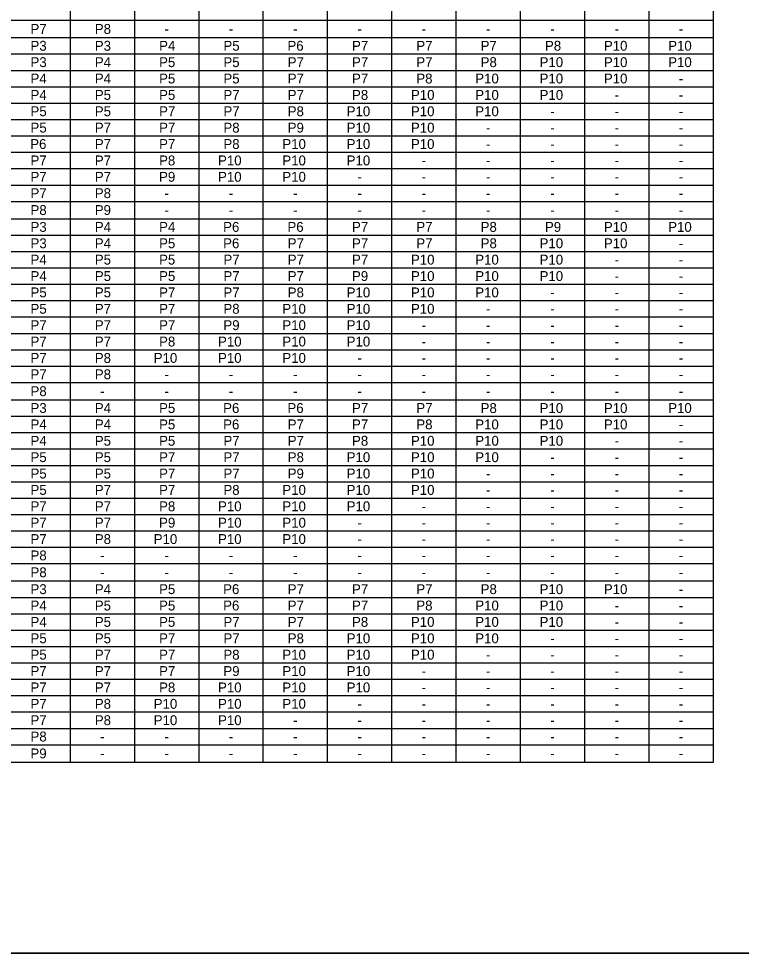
# Model space of a CAD drawing. Extents: x 637580 to 641008, y 294594 to 295782.
# Drawn here: x 639502.8 to 639722, y 295202.6 to 295486.4 of the extents above; entities that cross this region are included whole.
import ezdxf

# ---------------------------------------------------------------- set-up
doc = ezdxf.new("R2010")
doc.units = 0
doc.layers.add('1', color=7, linetype='Continuous')
doc.layers.add('2', color=7, linetype='Continuous')

msp = doc.modelspace()

# ---------------------------------------------------------------- linework, layer by layer
at = {"layer": '1'}
for p, q in [((639713.6, 295260.68), (639713.6, 295724.98)), ((639346.67, 295480.64), (639713.6, 295480.64)), ((639346.67, 295425.65), (639713.6, 295425.65)), ((639346.67, 295370.66), (639713.6, 295370.66)), ((639346.67, 295315.67), (639713.6, 295315.67)), ((639346.67, 295260.68), (639713.6, 295260.68)), ((640088.31, 295202.63), (639302.31, 295202.63)), ((639302.31, 295202.63), (639888.31, 295202.63))]:
    msp.add_line(p, q, dxfattribs=at)
at = {"layer": '2'}
for p, q in [((639518.52, 295260.68), (639518.52, 295709.96)), ((639538.03, 295260.68), (639538.03, 295709.96)), ((639557.54, 295260.68), (639557.54, 295709.96)), ((639577.04, 295260.68), (639577.04, 295709.96)), ((639596.55, 295260.68), (639596.55, 295709.96)), ((639616.06, 295260.68), (639616.06, 295709.96)), ((639635.57, 295260.68), (639635.57, 295709.96)), ((639655.07, 295260.68), (639655.07, 295709.96)), ((639674.58, 295260.68), (639674.58, 295709.96)), ((639694.09, 295260.68), (639694.09, 295709.96)), ((639373.47, 295485.9), (639713.6, 295485.9)), ((639373.47, 295475.66), (639713.6, 295475.66)), ((639373.47, 295470.69), (639713.6, 295470.69)), ((639373.47, 295465.72), (639713.6, 295465.72)), ((639373.47, 295460.75), (639713.6, 295460.75)), ((639373.47, 295455.77), (639713.6, 295455.77)), ((639373.47, 295450.8), (639713.6, 295450.8)), ((639373.47, 295445.83), (639713.6, 295445.83)), ((639373.47, 295440.86), (639713.6, 295440.86)), ((639373.47, 295435.88), (639713.6, 295435.88)), ((639373.47, 295430.91), (639713.6, 295430.91)), ((639373.47, 295420.67), (639713.6, 295420.67)), ((639373.47, 295415.7), (639713.6, 295415.7)), ((639373.47, 295410.73), (639713.6, 295410.73)), ((639373.47, 295405.76), (639713.6, 295405.76)), ((639373.47, 295400.78), (639713.6, 295400.78)), ((639373.47, 295395.81), (639713.6, 295395.81)), ((639373.47, 295390.84), (639713.6, 295390.84)), ((639373.47, 295385.87), (639713.6, 295385.87)), ((639373.47, 295380.89), (639713.6, 295380.89)), ((639373.47, 295375.92), (639713.6, 295375.92)), ((639373.47, 295365.68), (639713.6, 295365.68)), ((639373.47, 295360.71), (639713.6, 295360.71)), ((639373.47, 295355.74), (639713.6, 295355.74)), ((639373.47, 295350.77), (639713.6, 295350.77)), ((639373.47, 295345.79), (639713.6, 295345.79)), ((639373.47, 295340.82), (639713.6, 295340.82)), ((639373.47, 295335.85), (639713.6, 295335.85)), ((639373.47, 295330.88), (639713.6, 295330.88)), ((639373.47, 295325.9), (639713.6, 295325.9)), ((639373.47, 295320.93), (639713.6, 295320.93)), ((639373.47, 295310.69), (639713.6, 295310.69)), ((639373.47, 295305.72), (639713.6, 295305.72)), ((639373.47, 295300.75), (639713.6, 295300.75)), ((639373.47, 295295.78), (639713.6, 295295.78)), ((639373.47, 295290.8), (639713.6, 295290.8)), ((639373.47, 295285.83), (639713.6, 295285.83)), ((639373.47, 295280.86), (639713.6, 295280.86)), ((639373.47, 295275.89), (639713.6, 295275.89)), ((639373.47, 295270.91), (639713.6, 295270.91)), ((639373.47, 295265.94), (639713.6, 295265.94))]:
    msp.add_line(p, q, dxfattribs=at)

# ---------------------------------------------------------------- texts
at = {"layer": '1'}
for s, p in [('P7', (639506.42, 295481.77)), ('P8', (639525.93, 295481.77)), ('-', (639547.05, 295481.77)), ('-', (639566.56, 295481.77)), ('-', (639586.07, 295481.77)), ('-', (639605.57, 295481.77)), ('-', (639625.08, 295481.77)), ('-', (639644.59, 295481.77)), ('-', (639664.1, 295481.77)), ('-', (639683.6, 295481.77)), ('-', (639703.11, 295481.77)), ('P3', (639506.42, 295476.65)), ('P3', (639525.93, 295476.65)), ('P4', (639545.43, 295476.65)), ('P5', (639564.94, 295476.65)), ('P6', (639584.36, 295476.65)), ('P7', (639603.95, 295476.65)), ('P7', (639623.46, 295476.65)), ('P7', (639642.97, 295476.65)), ('P8', (639662.48, 295476.65)), ('P10', (639680.35, 295476.65)), ('P10', (639699.86, 295476.65)), ('P3', (639506.42, 295471.68)), ('P4', (639525.93, 295471.68)), ('P5', (639545.43, 295471.68)), ('P5', (639564.94, 295471.68)), ('P7', (639584.45, 295471.68)), ('P7', (639603.95, 295471.68)), ('P7', (639623.46, 295471.68)), ('P8', (639642.97, 295471.68)), ('P10', (639660.85, 295471.68)), ('P10', (639680.35, 295471.68)), ('P10', (639699.86, 295471.68)), ('P4', (639506.42, 295466.71)), ('P4', (639525.93, 295466.71)), ('P5', (639545.43, 295466.71)), ('P5', (639564.94, 295466.71)), ('P7', (639584.45, 295466.71)), ('P7', (639603.95, 295466.71)), ('P8', (639623.46, 295466.71)), ('P10', (639641.34, 295466.71)), ('P10', (639660.85, 295466.71)), ('P10', (639680.35, 295466.71)), ('-', (639703.11, 295466.71)), ('P4', (639506.42, 295461.73)), ('P5', (639525.93, 295461.73)), ('P5', (639545.43, 295461.73)), ('P7', (639564.94, 295461.73)), ('P7', (639584.45, 295461.73)), ('P8', (639603.95, 295461.73)), ('P10', (639621.83, 295461.73)), ('P10', (639641.34, 295461.73)), ('P10', (639660.85, 295461.73)), ('-', (639683.6, 295461.73)), ('-', (639703.11, 295461.73)), ('P5', (639506.42, 295456.76)), ('P5', (639525.93, 295456.76)), ('P7', (639545.43, 295456.76)), ('P7', (639564.94, 295456.76)), ('P8', (639584.45, 295456.76)), ('P10', (639602.33, 295456.76)), ('P10', (639621.83, 295456.76)), ('P10', (639641.34, 295456.76)), ('-', (639664.1, 295456.76)), ('-', (639683.6, 295456.76)), ('-', (639703.11, 295456.76)), ('P5', (639506.42, 295451.79)), ('P7', (639525.93, 295451.79)), ('P7', (639545.43, 295451.79)), ('P8', (639564.94, 295451.79)), ('P9', (639584.44, 295451.79)), ('P10', (639602.33, 295451.79)), ('P10', (639621.83, 295451.79)), ('-', (639644.59, 295451.79)), ('-', (639664.1, 295451.79)), ('-', (639683.6, 295451.79)), ('-', (639703.11, 295451.79)), ('P6', (639506.33, 295446.82)), ('P7', (639525.93, 295446.82)), ('P7', (639545.43, 295446.82)), ('P8', (639564.94, 295446.82)), ('P10', (639582.82, 295446.82)), ('P10', (639602.33, 295446.82)), ('P10', (639621.83, 295446.82)), ('-', (639644.59, 295446.82)), ('-', (639664.1, 295446.82)), ('-', (639683.6, 295446.82)), ('-', (639703.11, 295446.82)), ('P7', (639506.42, 295441.84)), ('P7', (639525.93, 295441.84)), ('P8', (639545.43, 295441.84)), ('P10', (639563.31, 295441.84)), ('P10', (639582.82, 295441.84)), ('P10', (639602.33, 295441.84)), ('-', (639625.08, 295441.84)), ('-', (639644.59, 295441.84)), ('-', (639664.1, 295441.84)), ('-', (639683.6, 295441.84)), ('-', (639703.11, 295441.84)), ('P7', (639506.42, 295436.87)), ('P7', (639525.93, 295436.87)), ('P9', (639545.42, 295436.87)), ('P10', (639563.31, 295436.87)), ('P10', (639582.82, 295436.87)), ('-', (639605.57, 295436.87)), ('-', (639625.08, 295436.87)), ('-', (639644.59, 295436.87)), ('-', (639664.1, 295436.87)), ('-', (639683.6, 295436.87)), ('-', (639703.11, 295436.87)), ('P7', (639506.42, 295431.9)), ('P8', (639525.93, 295431.9)), ('-', (639547.05, 295431.9)), ('-', (639566.56, 295431.9)), ('-', (639586.07, 295431.9)), ('-', (639605.57, 295431.9)), ('-', (639625.08, 295431.9)), ('-', (639644.59, 295431.9)), ('-', (639664.1, 295431.9)), ('-', (639683.6, 295431.9)), ('-', (639703.11, 295431.9)), ('P8', (639506.42, 295426.78)), ('P9', (639525.91, 295426.78)), ('-', (639547.05, 295426.78)), ('-', (639566.56, 295426.78)), ('-', (639586.07, 295426.78)), ('-', (639605.57, 295426.78)), ('-', (639625.08, 295426.78)), ('-', (639644.59, 295426.78)), ('-', (639664.1, 295426.78)), ('-', (639683.6, 295426.78)), ('-', (639703.11, 295426.78)), ('P3', (639506.42, 295421.66)), ('P4', (639525.93, 295421.66)), ('P4', (639545.43, 295421.66)), ('P6', (639564.86, 295421.66)), ('P6', (639584.36, 295421.66)), ('P7', (639603.95, 295421.66)), ('P7', (639623.46, 295421.66)), ('P8', (639642.97, 295421.66)), ('P9', (639662.47, 295421.66)), ('P10', (639680.35, 295421.66)), ('P10', (639699.86, 295421.66)), ('P3', (639506.42, 295416.69)), ('P4', (639525.93, 295416.69)), ('P5', (639545.43, 295416.69)), ('P6', (639564.86, 295416.69)), ('P7', (639584.45, 295416.69)), ('P7', (639603.95, 295416.69)), ('P7', (639623.46, 295416.69)), ('P8', (639642.97, 295416.69)), ('P10', (639660.85, 295416.69)), ('P10', (639680.35, 295416.69)), ('-', (639703.11, 295416.69)), ('P4', (639506.42, 295411.72)), ('P5', (639525.93, 295411.72)), ('P5', (639545.43, 295411.72)), ('P7', (639564.94, 295411.72)), ('P7', (639584.45, 295411.72)), ('P7', (639603.95, 295411.72)), ('P10', (639621.83, 295411.72)), ('P10', (639641.34, 295411.72)), ('P10', (639660.85, 295411.72)), ('-', (639683.6, 295411.72)), ('-', (639703.11, 295411.72)), ('P4', (639506.42, 295406.74)), ('P5', (639525.93, 295406.74)), ('P5', (639545.43, 295406.74)), ('P7', (639564.94, 295406.74)), ('P7', (639584.45, 295406.74)), ('P9', (639603.94, 295406.74)), ('P10', (639621.83, 295406.74)), ('P10', (639641.34, 295406.74)), ('P10', (639660.85, 295406.74)), ('-', (639683.6, 295406.74)), ('-', (639703.11, 295406.74)), ('P5', (639506.42, 295401.77)), ('P5', (639525.93, 295401.77)), ('P7', (639545.43, 295401.77)), ('P7', (639564.94, 295401.77)), ('P8', (639584.45, 295401.77)), ('P10', (639602.33, 295401.77)), ('P10', (639621.83, 295401.77)), ('P10', (639641.34, 295401.77)), ('-', (639664.1, 295401.77)), ('-', (639683.6, 295401.77)), ('-', (639703.11, 295401.77)), ('P5', (639506.42, 295396.8)), ('P7', (639525.93, 295396.8)), ('P7', (639545.43, 295396.8)), ('P8', (639564.94, 295396.8)), ('P10', (639582.82, 295396.8)), ('P10', (639602.33, 295396.8)), ('P10', (639621.83, 295396.8)), ('-', (639644.59, 295396.8)), ('-', (639664.1, 295396.8)), ('-', (639683.6, 295396.8)), ('-', (639703.11, 295396.8)), ('P7', (639506.42, 295391.83)), ('P7', (639525.93, 295391.83)), ('P7', (639545.43, 295391.83)), ('P9', (639564.93, 295391.83)), ('P10', (639582.82, 295391.83)), ('P10', (639602.33, 295391.83)), ('-', (639625.08, 295391.83)), ('-', (639644.59, 295391.83)), ('-', (639664.1, 295391.83)), ('-', (639683.6, 295391.83)), ('-', (639703.11, 295391.83)), ('P7', (639506.42, 295386.85)), ('P7', (639525.93, 295386.85)), ('P8', (639545.43, 295386.85)), ('P10', (639563.31, 295386.85)), ('P10', (639582.82, 295386.85)), ('P10', (639602.33, 295386.85)), ('-', (639625.08, 295386.85)), ('-', (639644.59, 295386.85)), ('-', (639664.1, 295386.85)), ('-', (639683.6, 295386.85)), ('-', (639703.11, 295386.85)), ('P7', (639506.42, 295381.88)), ('P8', (639525.93, 295381.88)), ('P10', (639543.8, 295381.88)), ('P10', (639563.31, 295381.88)), ('P10', (639582.82, 295381.88)), ('-', (639605.57, 295381.88)), ('-', (639625.08, 295381.88)), ('-', (639644.59, 295381.88)), ('-', (639664.1, 295381.88)), ('-', (639683.6, 295381.88)), ('-', (639703.11, 295381.88)), ('P7', (639506.42, 295376.91)), ('P8', (639525.93, 295376.91)), ('-', (639547.05, 295376.91)), ('-', (639566.56, 295376.91)), ('-', (639586.07, 295376.91)), ('-', (639605.57, 295376.91)), ('-', (639625.08, 295376.91)), ('-', (639644.59, 295376.91)), ('-', (639664.1, 295376.91)), ('-', (639683.6, 295376.91)), ('-', (639703.11, 295376.91)), ('P8', (639506.42, 295371.79)), ('-', (639527.54, 295371.79)), ('-', (639547.05, 295371.79)), ('-', (639566.56, 295371.79)), ('-', (639586.07, 295371.79)), ('-', (639605.57, 295371.79)), ('-', (639625.08, 295371.79)), ('-', (639644.59, 295371.79)), ('-', (639664.1, 295371.79)), ('-', (639683.6, 295371.79)), ('-', (639703.11, 295371.79)), ('P3', (639506.42, 295366.67)), ('P4', (639525.93, 295366.67)), ('P5', (639545.43, 295366.67)), ('P6', (639564.86, 295366.67)), ('P6', (639584.36, 295366.67)), ('P7', (639603.95, 295366.67)), ('P7', (639623.46, 295366.67)), ('P8', (639642.97, 295366.67)), ('P10', (639660.85, 295366.67)), ('P10', (639680.35, 295366.67)), ('P10', (639699.86, 295366.67)), ('P4', (639506.42, 295361.7)), ('P4', (639525.93, 295361.7)), ('P5', (639545.43, 295361.7)), ('P6', (639564.86, 295361.7)), ('P7', (639584.45, 295361.7)), ('P7', (639603.95, 295361.7)), ('P8', (639623.46, 295361.7)), ('P10', (639641.34, 295361.7)), ('P10', (639660.85, 295361.7)), ('P10', (639680.35, 295361.7)), ('-', (639703.11, 295361.7)), ('P4', (639506.42, 295356.73)), ('P5', (639525.93, 295356.73)), ('P5', (639545.43, 295356.73)), ('P7', (639564.94, 295356.73)), ('P7', (639584.45, 295356.73)), ('P8', (639603.95, 295356.73)), ('P10', (639621.83, 295356.73)), ('P10', (639641.34, 295356.73)), ('P10', (639660.85, 295356.73)), ('-', (639683.6, 295356.73)), ('-', (639703.11, 295356.73)), ('P5', (639506.42, 295351.75)), ('P5', (639525.93, 295351.75)), ('P7', (639545.43, 295351.75)), ('P7', (639564.94, 295351.75)), ('P8', (639584.45, 295351.75)), ('P10', (639602.33, 295351.75)), ('P10', (639621.83, 295351.75)), ('P10', (639641.34, 295351.75)), ('-', (639664.1, 295351.75)), ('-', (639683.6, 295351.75)), ('-', (639703.11, 295351.75)), ('P5', (639506.42, 295346.78)), ('P5', (639525.93, 295346.78)), ('P7', (639545.43, 295346.78)), ('P7', (639564.94, 295346.78)), ('P9', (639584.44, 295346.78)), ('P10', (639602.33, 295346.78)), ('P10', (639621.83, 295346.78)), ('-', (639644.59, 295346.78)), ('-', (639664.1, 295346.78)), ('-', (639683.6, 295346.78)), ('-', (639703.11, 295346.78)), ('P5', (639506.42, 295341.81)), ('P7', (639525.93, 295341.81)), ('P7', (639545.43, 295341.81)), ('P8', (639564.94, 295341.81)), ('P10', (639582.82, 295341.81)), ('P10', (639602.33, 295341.81)), ('P10', (639621.83, 295341.81)), ('-', (639644.59, 295341.81)), ('-', (639664.1, 295341.81)), ('-', (639683.6, 295341.81)), ('-', (639703.11, 295341.81)), ('P7', (639506.42, 295336.84)), ('P7', (639525.93, 295336.84)), ('P8', (639545.43, 295336.84)), ('P10', (639563.31, 295336.84)), ('P10', (639582.82, 295336.84)), ('P10', (639602.33, 295336.84)), ('-', (639625.08, 295336.84)), ('-', (639644.59, 295336.84)), ('-', (639664.1, 295336.84)), ('-', (639683.6, 295336.84)), ('-', (639703.11, 295336.84)), ('P7', (639506.42, 295331.86)), ('P7', (639525.93, 295331.86)), ('P9', (639545.42, 295331.86)), ('P10', (639563.31, 295331.86)), ('P10', (639582.82, 295331.86)), ('-', (639605.57, 295331.86)), ('-', (639625.08, 295331.86)), ('-', (639644.59, 295331.86)), ('-', (639664.1, 295331.86)), ('-', (639683.6, 295331.86)), ('-', (639703.11, 295331.86)), ('P7', (639506.42, 295326.89)), ('P8', (639525.93, 295326.89)), ('P10', (639543.8, 295326.89)), ('P10', (639563.31, 295326.89)), ('P10', (639582.82, 295326.89)), ('-', (639605.57, 295326.89)), ('-', (639625.08, 295326.89)), ('-', (639644.59, 295326.89)), ('-', (639664.1, 295326.89)), ('-', (639683.6, 295326.89)), ('-', (639703.11, 295326.89)), ('P8', (639506.42, 295321.92)), ('-', (639527.54, 295321.92)), ('-', (639547.05, 295321.92)), ('-', (639566.56, 295321.92)), ('-', (639586.07, 295321.92)), ('-', (639605.57, 295321.92)), ('-', (639625.08, 295321.92)), ('-', (639644.59, 295321.92)), ('-', (639664.1, 295321.92)), ('-', (639683.6, 295321.92)), ('-', (639703.11, 295321.92)), ('P8', (639506.42, 295316.8)), ('-', (639527.54, 295316.8)), ('-', (639547.05, 295316.8)), ('-', (639566.56, 295316.8)), ('-', (639586.07, 295316.8)), ('-', (639605.57, 295316.8)), ('-', (639625.08, 295316.8)), ('-', (639644.59, 295316.8)), ('-', (639664.1, 295316.8)), ('-', (639683.6, 295316.8)), ('-', (639703.11, 295316.8)), ('P3', (639506.42, 295311.68)), ('P4', (639525.93, 295311.68)), ('P5', (639545.43, 295311.68)), ('P6', (639564.86, 295311.68)), ('P7', (639584.45, 295311.68)), ('P7', (639603.95, 295311.68)), ('P7', (639623.46, 295311.68)), ('P8', (639642.97, 295311.68)), ('P10', (639660.85, 295311.68)), ('P10', (639680.35, 295311.68)), ('-', (639703.11, 295311.68)), ('P4', (639506.42, 295306.71)), ('P5', (639525.93, 295306.71)), ('P5', (639545.43, 295306.71)), ('P6', (639564.86, 295306.71)), ('P7', (639584.45, 295306.71)), ('P7', (639603.95, 295306.71)), ('P8', (639623.46, 295306.71)), ('P10', (639641.34, 295306.71)), ('P10', (639660.85, 295306.71)), ('-', (639683.6, 295306.71)), ('-', (639703.11, 295306.71)), ('P4', (639506.42, 295301.74)), ('P5', (639525.93, 295301.74)), ('P5', (639545.43, 295301.74)), ('P7', (639564.94, 295301.74)), ('P7', (639584.45, 295301.74)), ('P8', (639603.95, 295301.74)), ('P10', (639621.83, 295301.74)), ('P10', (639641.34, 295301.74)), ('P10', (639660.85, 295301.74)), ('-', (639683.6, 295301.74)), ('-', (639703.11, 295301.74)), ('P5', (639506.42, 295296.76)), ('P5', (639525.93, 295296.76)), ('P7', (639545.43, 295296.76)), ('P7', (639564.94, 295296.76)), ('P8', (639584.45, 295296.76)), ('P10', (639602.33, 295296.76)), ('P10', (639621.83, 295296.76)), ('P10', (639641.34, 295296.76)), ('-', (639664.1, 295296.76)), ('-', (639683.6, 295296.76)), ('-', (639703.11, 295296.76)), ('P5', (639506.42, 295291.79)), ('P7', (639525.93, 295291.79)), ('P7', (639545.43, 295291.79)), ('P8', (639564.94, 295291.79)), ('P10', (639582.82, 295291.79)), ('P10', (639602.33, 295291.79)), ('P10', (639621.83, 295291.79)), ('-', (639644.59, 295291.79)), ('-', (639664.1, 295291.79)), ('-', (639683.6, 295291.79)), ('-', (639703.11, 295291.79)), ('P7', (639506.42, 295286.82)), ('P7', (639525.93, 295286.82)), ('P7', (639545.43, 295286.82)), ('P9', (639564.93, 295286.82)), ('P10', (639582.82, 295286.82)), ('P10', (639602.33, 295286.82)), ('-', (639625.08, 295286.82)), ('-', (639644.59, 295286.82)), ('-', (639664.1, 295286.82)), ('-', (639683.6, 295286.82)), ('-', (639703.11, 295286.82)), ('P7', (639506.42, 295281.85)), ('P7', (639525.93, 295281.85)), ('P8', (639545.43, 295281.85)), ('P10', (639563.31, 295281.85)), ('P10', (639582.82, 295281.85)), ('P10', (639602.33, 295281.85)), ('-', (639625.08, 295281.85)), ('-', (639644.59, 295281.85)), ('-', (639664.1, 295281.85)), ('-', (639683.6, 295281.85)), ('-', (639703.11, 295281.85)), ('P7', (639506.42, 295276.87)), ('P8', (639525.93, 295276.87)), ('P10', (639543.8, 295276.87)), ('P10', (639563.31, 295276.87)), ('P10', (639582.82, 295276.87)), ('-', (639605.57, 295276.87)), ('-', (639625.08, 295276.87)), ('-', (639644.59, 295276.87)), ('-', (639664.1, 295276.87)), ('-', (639683.6, 295276.87)), ('-', (639703.11, 295276.87)), ('P7', (639506.42, 295271.9)), ('P8', (639525.93, 295271.9)), ('P10', (639543.8, 295271.9)), ('P10', (639563.31, 295271.9)), ('-', (639586.07, 295271.9)), ('-', (639605.57, 295271.9)), ('-', (639625.08, 295271.9)), ('-', (639644.59, 295271.9)), ('-', (639664.1, 295271.9)), ('-', (639683.6, 295271.9)), ('-', (639703.11, 295271.9)), ('P8', (639506.42, 295266.93)), ('-', (639527.54, 295266.93)), ('-', (639547.05, 295266.93)), ('-', (639566.56, 295266.93)), ('-', (639586.07, 295266.93)), ('-', (639605.57, 295266.93)), ('-', (639625.08, 295266.93)), ('-', (639644.59, 295266.93)), ('-', (639664.1, 295266.93)), ('-', (639683.6, 295266.93)), ('-', (639703.11, 295266.93)), ('P9', (639506.41, 295261.81)), ('-', (639527.54, 295261.81)), ('-', (639547.05, 295261.81)), ('-', (639566.56, 295261.81)), ('-', (639586.07, 295261.81)), ('-', (639605.57, 295261.81)), ('-', (639625.08, 295261.81)), ('-', (639644.59, 295261.81)), ('-', (639664.1, 295261.81)), ('-', (639683.6, 295261.81)), ('-', (639703.11, 295261.81))]:
    msp.add_text(s, height=3, dxfattribs=at).set_placement(p)

doc.saveas('drawing.dxf')
